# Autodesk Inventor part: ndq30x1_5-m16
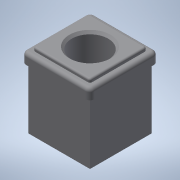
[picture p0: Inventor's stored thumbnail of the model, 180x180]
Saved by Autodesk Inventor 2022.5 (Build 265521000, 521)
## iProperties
Created: 2016-12
Part Number: ndq30x1_5-m16
Material: 一般
Document SubType Name: Modeling
Designer: imaocorp
Density: 1 g/cm^3
Appearance: 既定
Author: imaocorp
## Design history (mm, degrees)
node "ndq30x1_5-m16.x_t1"
node "ndq30x1_5-m16"
node "Base1"
